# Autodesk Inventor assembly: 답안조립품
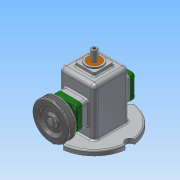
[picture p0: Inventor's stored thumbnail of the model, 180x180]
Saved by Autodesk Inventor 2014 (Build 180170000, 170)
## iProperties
Created: 2018-07
Part Number: 답안조립품
Document SubType Name: Assembly
Designer: user
Author: user
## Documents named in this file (16)
- C:\Users\user\Desktop\480707V1005\답안조립품.iam
- C:\Users\user\Desktop\480707V1005\본체.ipt
- C:\Users\user\Desktop\480707V1005\앞커버.ipt
- C:\Users\user\Desktop\480707V1005\뒤커버.ipt
- C:\Users\user\Desktop\480707V1005\베어링 12x32x10.ipt
- C:\Users\user\Desktop\480707V1005\오일 실 12 25 7.ipt
- C:\Users\user\Desktop\480707V1005\편심축.ipt
- C:\Users\user\Desktop\480707V1005\V벨트풀리.ipt
- C:\Users\user\Desktop\480707V1005\링크.ipt
- C:\Users\user\Desktop\480707V1005\슬라이드.ipt
- C:\Users\user\Desktop\480707V1005\부시.ipt
- C:\Users\user\Desktop\480707V1005\핀 5x18.ipt
- C:\Users\user\Desktop\480707V1005\고정핀 1.2x8.ipt
- C:\Users\user\Desktop\480707V1005\키 4x4x10.ipt
- C:\Users\user\Desktop\480707V1005\볼트 M4.ipt
- C:\Users\user\Desktop\480707V1005\멈춤나사 M3x8.ipt
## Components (3 placed, 3 different names)
1. V벨트풀리:1 — 플러쉬:2
2. 핀 5x18:1
3. 고정핀 1.2x8:1
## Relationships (1: Flush 1)
- 플러쉬:2 [Flush]: V벨트풀리:1
